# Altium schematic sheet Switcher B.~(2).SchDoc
size 431 x 279 mm; Organization: UTVATE; Address1: ADDRESS 1; Address2: ADDRESS 2; Address3: ADDRESS 3; Address4: ADDRESS 4; Revision: -; SheetNumber: 1; SheetTotal: 1; ENG_APP_DATE: YYYY/MM/DD; DSN_APP_DATE: YYYY/MM/DD; CHK_APP_DATE: YYYY/MM/DD
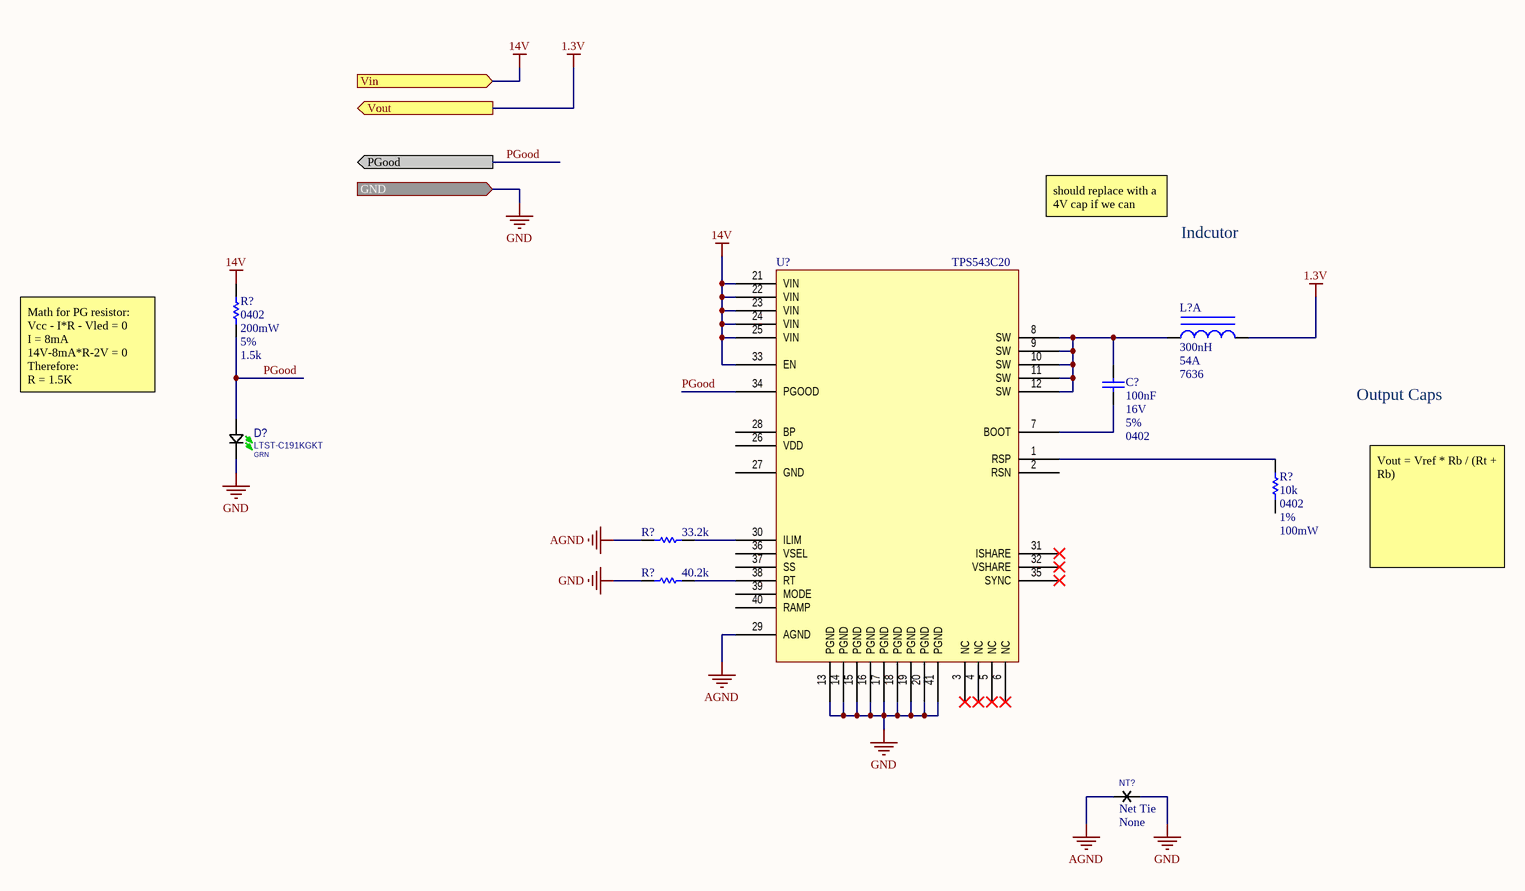
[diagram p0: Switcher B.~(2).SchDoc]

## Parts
(Parts that share a designator on the sheet are numbered #1, #2 ... from top to bottom, then left to right.)
C?  value 100nF  Voltage Rating: 16V  Tolerance: 5%  Case/Package: 0402  [CAP_0402_Nominal]  (hidden comment: GRM155R71C104JA88D)
D?  LTST-C191KGKT  Color: GRN  [DIOC1608X06N]
L?  value 300nH  Max Current: 54A  Case/Package: 7636  [COIL-SER2009-3_V]  (hidden comment: 300nH Inductor)  (part A of 2)
NT?  Net Tie  Manufacturer: None  [Net Tie-Footprint-1]  (net tie, no BOM)
R?#1  value 1.5k  Case/Package: 0402  Power: 200mW  Tolerance: 5%  [RESC1005X40X25ML05T10]  (hidden comment: RCS04021K50JNED)
R?#2  value 10k  Case/Package: 0402  Tolerance: 1%  Power: 100mW  [RES_0402_Most]  (hidden comment: ERJ-2RKF1002X)
R?#3  value 33.2k  [RES_0402_Most]  (hidden comment: CRCW040233K2FKED)
R?#4  value 40.2k  [RES_0402_Nominal]  (hidden comment: Res 40.2K 0402)
U?  TPS543C20  [TPS543C20 -Footprint-1]

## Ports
GND (in), PGood (out), Vin (in), Vout (out)

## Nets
1.3V: L?.2 ; port Vout
14V: R?#1.2 U?.21(VIN) U?.22(VIN) U?.23(VIN) U?.24(VIN) U?.25(VIN) U?.33(EN) ; port Vin
AGND: NT?.1 R?#3.1 U?.29(AGND)
GND: D?.1 NT?.2 R?#4.1 U?.13(PGND) U?.14(PGND) U?.15(PGND) U?.16(PGND) U?.17(PGND) U?.18(PGND) U?.19(PGND) U?.20(PGND) U?.41(PGND) ; port GND
PGood: D?.2 R?#1.1 U?.34(PGOOD) ; port PGood
NetC?_1: C?.1 U?.7(BOOT)
NetC?_2: C?.2 L?.1 U?.8(SW) U?.9(SW) U?.10(SW) U?.11(SW) U?.12(SW)
NetR?#2_1: R?#2.1 U?.1(RSP)
NetR?#3_2: R?#3.2 U?.30(ILIM)
NetR?#4_2: R?#4.2 U?.38(RT)

Not connected (* = marked no-connect by the designer): R?#2 2; U? 2(RSN) 3(NC)* 4(NC)* 5(NC)* 6(NC)* 26(VDD) 27(GND) 28(BP) 31(ISHARE)* 32(VSHARE)* 35(SYNC)* 36(VSEL) 37(SS) 39(MODE) 40(RAMP)

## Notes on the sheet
- should replace with a 4V cap if we can
- Indcutor
- Math for PG resistor:
  Vcc - I*R - Vled = 0
  I = 8mA
  14V-8mA*R-2V = 0
  Therefore:
  R = 1.5K
- Output Caps
- Vout = Vref * Rb / (Rt + Rb)

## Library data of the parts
C? = CMP-001-00001-23: Cap 100nF 0402 16V; Manufacturer: Murata; Capacitor Type: Ceramic; Dielectric: X7R
D? = CMP-011-0002-3: LED, GREEN, 0603, 2V; Manufacturer: Lite-On Inc.; Forward Current: 20mA
L? = CMP-006-00014-1: General Purpose Inductor, 0.3uH, 20%, 1 Element, Ferrite-Core, SMD, 7636; Manufacturer Part Number: SER2009-301MLD; Manufacturer: CoilCraft; Case/Size Code: 7674; Inductor Application: POWER INDUCTOR; Package Width: 18.7mm; Max Current Rating: 100A; Package Length: 19.18mm; Shielding: Unshielded; Shape/Size Description: RECTANGULAR PACKAGE; Self Resonant Frequency: 550MHz; Package Height: 8.64mm; Channels: 1; Test Frequency: 100kHz; DC Resistance (DCR): 0.74mR
NT? = CMP-006-0011-2: All Copper net tie to join two nets together in a specific location
R?#1 = CMP-009-00072-1: Res 1.5K 0402; Manufacturer: Vishay Dale
R?#2 = CMP-009-00012-12: Res 10k 0402; Manufacturer: Panasonic; Temperature Coefficient: 100ppm/°C; Voltage Rating: 50V
R?#3 = CMP-009-00011-12: Res 33.2k 0402; Manufacturer: Vishay Dale; Temperature Coefficient: 100ppm/°C; Power: 63mW; Tolerance: 1%; Voltage Rating: 50V
R?#4 = CMP-009-00082-1: 40.2K 0402; Manufacturer Part Number: RCS040240K2FKED; Manufacturer: Vishay Dale; Power: 200mW; Tolerance: 1%
U? = CMP-019-00006-1: Switching Regulator, Current-mode, 40A, 2000kHz Switching Freq-Max, PQCC40; Manufacturer: Texas Instruments; Min Supply Voltage: 4V; Output Voltage: 5.5V; Max Supply Voltage: 16V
